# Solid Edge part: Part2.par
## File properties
Author: CADCIM
Template: Normal.par
Last saved by: CADCIM
Revision: 13
Application: Solid Edge
Accuracy: 0.99
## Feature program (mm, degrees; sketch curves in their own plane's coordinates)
sketch for "unnamed Protrusion 1" plane through (0, 0, 0) normal (0, -1, 0) x-axis (1, 0, 0)
  line (-41.5864, -1.056) -> (-41.5864, 10.944)
  line (-41.5864, 10.944) -> (58.4136, 10.944)
  arc centre (58.4136, 25.944) radius 15 from (58.4136, 10.944) to (70.6346, 34.6415) ccw
  line (70.6346, 34.6415) -> (76.9484, 45.5772)
  arc centre (58.4136, 25.944) radius 27 from (58.4136, -1.056) to (76.9484, 45.5772) ccw
  line (58.4136, -1.056) -> (-41.5864, -1.056)
extrude "unnamed Protrusion 1" add finite 50 along +normal
sketch for "ExtrudedProtrusion_3" #1 plane through (-44.5864, -25, 4.1402) normal (-0.866025, 0, -0.5) x-axis (0, -1, 0)
  line (-15, 28) -> (-15, 73)
  arc centre (-10, 73) radius 5 from (-5, 73) to (-15, 73) ccw
  line (-5, 73) -> (-5, 36)
  line (-5, 36) -> (5, 36)
  line (5, 36) -> (5, 61)
  arc centre (10, 61) radius 5 from (5, 61) to (15, 61) cw
  line (15, 61) -> (15, 28)
  arc centre (0, 28) radius 15 from (-15, 28) to (15, 28) ccw
sketch for "ExtrudedProtrusion_3" #2 plane through (-44.5864, -25, 4.1402) normal (-0.866025, 0, -0.5) x-axis (0, -1, 0)
  arc centre (-19, 84) radius 6 from (-25, 84) to (-16.2055, 89.3095) cw
  line (-16.2055, 89.3095) -> (21.7945, 69.3095)
  arc centre (19, 64) radius 6 from (21.7945, 69.3095) to (25, 64) cw
  line (25, 64) -> (25, -6)
  line (25, -6) -> (-25, -6)
  line (-25, 84) -> (-25, -6)
extrude "ExtrudedProtrusion_3" add finite 12 along -normal
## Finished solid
Body 1: solid body, 20 faces, 54 edges, 36 vertices.
  Faces by surface: plane 13, cylinder 7
  Edges by curve: line 40, circle 14
Bounding box of the edges (mm): 175.000 x 50.000 x 89.138, from (-89.5864, -50, -1.056) to (85.4136, 0, 88.0824).
Cylindrical faces by radius (mm): R5 x2, R6 x2, R15 x2, R27 x1
Planar faces by outward normal: +y 3, +z 1, -y 3, -z 1, oblique 5
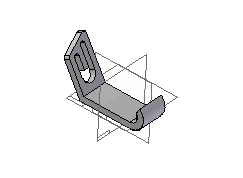
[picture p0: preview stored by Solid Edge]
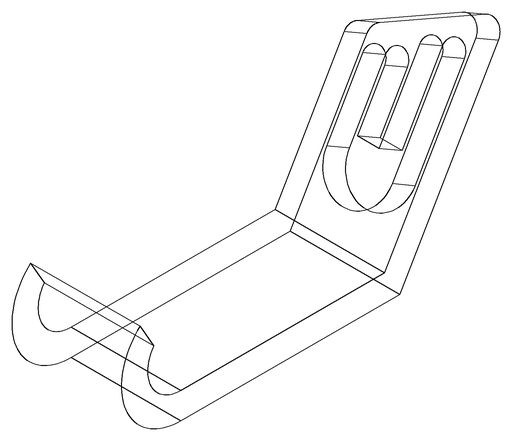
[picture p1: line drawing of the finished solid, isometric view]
